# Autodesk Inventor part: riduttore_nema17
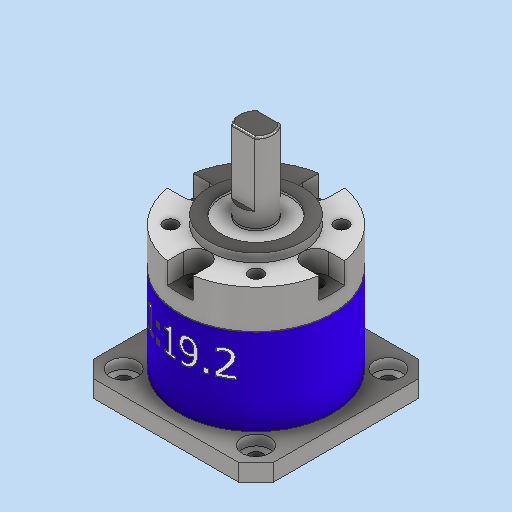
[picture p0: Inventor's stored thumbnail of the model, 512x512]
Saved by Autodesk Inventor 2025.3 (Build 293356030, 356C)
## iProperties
Created: 2026-01
Part Number: riduttore_nema17
Material: Generico
Document SubType Name: Modeling
Designer: R5800u
Density: 1 g/cm^3
Appearance: Default
Author: R5800u
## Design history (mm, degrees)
sketch "Schizzo1"
  geometry: L1 (21, 21)-(-21, 21); L2 (-21, 21)-(-21, -21); L3 (-21, -21)-(21, -21); L4 (21, -21)-(21, 21); L5 (21, 21)-(-21, -21); L6 (-21, 21)-(21, -21); 1 further point
  constraints: 12 end point, 2 midpoint, 2 parallel, 1 horizontal, 1 perpendicular
  dimensions: "d0" = 42 distance of L3.end L2.end; "d1" = 42 distance of L2.end L1.end
extrude "Estrusione1" new body sketch "Schizzo1" distance "d2" = 4; taper "d3" = 0 deg
sketch "Schizzo2"
  geometry: C1 r 18 at (0, 0); 1 further point
  constraints: 1 centre point, 1 coincident
  dimensions: "d4" = 36 diameter of C1
extrude "Estrusione2" join sketch "Schizzo2" distance "d5" = 29.3; taper "d6" = 0 deg
sketch "Schizzo3"
  geometry: C1 r 11 at (0, 0); 1 further point
  constraints: 1 centre point, 1 coincident
  dimensions: "d7" = 22 diameter of C1
extrude "Estrusione3" join sketch "Schizzo3" distance "d8" = 2; taper "d9" = 0 deg
sketch "Schizzo4"
  geometry: C1 r 4 at (0, 0); 1 further point
  constraints: 1 centre point, 1 coincident
  dimensions: "d10" = 8 diameter of C1
extrude "Estrusione4" new body sketch "Schizzo4" distance "d11" = 18.5; taper "d12" = 0 deg
sketch "Schizzo5"
  geometry: L1 (7.554, -3)-(-7.554, -3); L2 (-7.554, -3)-(-7.554, 3); L3 (-7.554, 3)-(7.554, 3); L4 (7.554, 3)-(7.554, -3); L5 (7.554, -3)-(-7.554, 3); L6 (-7.554, -3)-(7.554, 3); C1 r 4 at (0, 0) reference; 5 further points
  constraints: 12 end point, 2 midpoint, 2 parallel, 1 horizontal, 1 perpendicular
  dimensions: "d13" = 6 distance of L1.end L2.end
extrude "Estrusione5" cut sketch "Schizzo5" distance "d14" = 15; taper "d15" = 0 deg
sketch "Schizzo6"
  geometry: L1 (-14, -3)-(-17.748, -3); L2 (-14, 3)-(-17.748, 3); A1 r 3 centre (-14, 0) between (-14, -3) and (-14, 3); A2 r 18 centre (0, 0) between (-17.748, -3) and (-17.748, 3) reference; 1 further point
  constraints: 4 end point, 4 point on circle, 2 tangent, 1 centre point, 1 horizontal, 1 parallel
  dimensions: "d16" = 6 diameter of A1; "d17" = 14 distance of point (0, 0) A1.centre
extrude "Estrusione6" cut sketch "Schizzo6" distance "d18" = 5; taper "d19" = 0 deg
pattern_circular "Serie circolare1" dims angle "d21" = 360 deg
sketch "Schizzo7"
  geometry: L1 (10, -10)-(-10, -10); L2 (-10, -10)-(-10, 10); L3 (-10, 10)-(10, 10); L4 (10, 10)-(10, -10); L5 (10, -10)-(-10, 10); L6 (-10, -10)-(10, 10); C1 r 4 at (0, 0) reference; 1 further point
  constraints: 12 end point, 2 midpoint, 2 parallel, 1 horizontal, 1 perpendicular
  dimensions: "d23" = 20 distance of L2.end L3.end; "d24" = 20 distance of L1.end L2.end
hole "Foro1" sketch "Schizzo7" at (-10, 10), (-10, -10), (10, -10), (10, 10) diameter "d25" = 3.2; stored, may be unused: countersink angle "d29" = 90 deg, drill point angle "d31" = 118 deg; dims "d26" = 6, "d27" = 6.5, "d28" = 3.4, "d30" = 10
sketch "Schizzo8"
  geometry: A1 r 3 centre (-14, 0) between (-14, -3) and (-14, 3) reference; 1 further point
hole "Foro2" sketch "Schizzo8" at (-14, 0) diameter "d32" = 3.2; stored, may be unused: countersink angle "d36" = 90 deg, drill point angle "d38" = 118 deg; dims "d33" = 6, "d34" = 4, "d35" = 2, "d37" = 10
pattern_circular "Serie circolare2" dims angle "d40" = 360 deg
node "Piano di lavoro1"
sketch "Schizzo9"
  geometry: C1 r 17.9 at (0, 0); A1 r 18 centre (0, 0) between (3, -17.748) and (17.748, -3) reference; A2 r 18 centre (0, 0) between (3, -17.748) and (17.748, -3) reference; 1 further point
  constraints: 1 centre point
  dimensions: "d43" = 0.1 radial gap between concentric circles of A2 C1
extrude "Estrusione7" cut sketch "Schizzo9" distance "d44" = 0.1; taper "d45" = 0 deg
chamfer "Smusso1" distance "d46" = 4; stored, may be unused: second distance "d47" = 2, angle "d48" = 45 deg
sketch "Schizzo10"
  geometry: L1 (15.5, -15.5)-(-15.5, -15.5); L2 (-15.5, -15.5)-(-15.5, 15.5); L3 (-15.5, 15.5)-(15.5, 15.5); L4 (15.5, 15.5)-(15.5, -15.5); L5 (15.5, -15.5)-(-15.5, 15.5); L6 (-15.5, -15.5)-(15.5, 15.5); C1 r 4 at (0, 0) reference; 1 further point
  constraints: 12 end point, 2 midpoint, 2 parallel, 1 horizontal, 1 perpendicular
  dimensions: "d49" = 31 distance of L2.end L3.end; "d50" = 31 distance of L1.end L2.end
hole "Foro3" sketch "Schizzo10" at (15.5, -15.5), (15.5, 15.5), (-15.5, 15.5), (-15.5, -15.5) diameter "d51" = 3.2; stored, may be unused: countersink angle "d55" = 90 deg, drill point angle "d57" = 118 deg; dims "d52" = 6, "d53" = 6.5, "d54" = 2.4, "d56" = 10
sketch "Schizzo11"
  geometry: C1 r 4 at (0, 0) reference; C2 r 8 at (0, 0); 1 further point
  constraints: 1 centre point, 1 coincident
  dimensions: "d58" = 16 diameter of C2
extrude "Estrusione8" cut sketch "Schizzo11" distance "d59" = 0.5; taper "d60" = 0 deg
fillet "Raccordo1" dims "d61" = 0.4
feature "Filettatura1" dims "d62" = 10, "d63" = 0
feature "Filettatura2" dims "d64" = 10, "d65" = 0
feature "Filettatura3" dims "d66" = 10, "d67" = 0
feature "Filettatura4" dims "d68" = 10, "d69" = 0
feature "Filettatura5" dims "d70" = 10, "d71" = 0
feature "Filettatura6" dims "d72" = 10, "d73" = 0
feature "Filettatura7" dims "d74" = 10, "d75" = 0
feature "Filettatura8" dims "d76" = 10, "d77" = 0
feature "Filettatura9" dims "d78" = 4, "d79" = 0
feature "Filettatura10" dims "d80" = 4, "d81" = 0
feature "Filettatura11" dims "d82" = 4, "d83" = 0
feature "Filettatura12" dims "d84" = 4, "d85" = 0
sketch "Schizzo12"
  geometry: C1 r 4 at (0, 0) reference; C2 r 11 at (0, 0); 1 further point
  constraints: 1 centre point, 1 coincident
  dimensions: "d86" = 22 diameter of C2
extrude "Estrusione9" cut sketch "Schizzo12" distance "d87" = 2.5; taper "d88" = 0 deg
sketch "Schizzo13"
  geometry: C1 r 4 at (0, 0) reference; C2 r 5 at (0, 0); 1 further point
  constraints: 1 centre point, 1 coincident
  dimensions: "d89" = 10 diameter of C2
extrude "Estrusione10" cut sketch "Schizzo13" distance "d90" = 9.5; taper "d91" = 0 deg
node "Piano di lavoro2"
sketch "Schizzo14"
  geometry: L1 (4.854, 20.491)-(30.975, 20.491); L2 (30.975, 20.491)-(30.975, 11.776); L3 (30.975, 11.776)-(4.854, 11.776); L4 (4.854, 11.776)-(4.854, 20.491); 1 further point
  constraints: 2 other
feature "Sbalzo1" sketch "Schizzo14" dims "d10" = 8, "d93" = 0.1, "d94" = 0
node "Solido1"
node "Solido2"
node "Linea chiusa proiettata1"
other parameters: "d42" = -9, "d92" = 0
